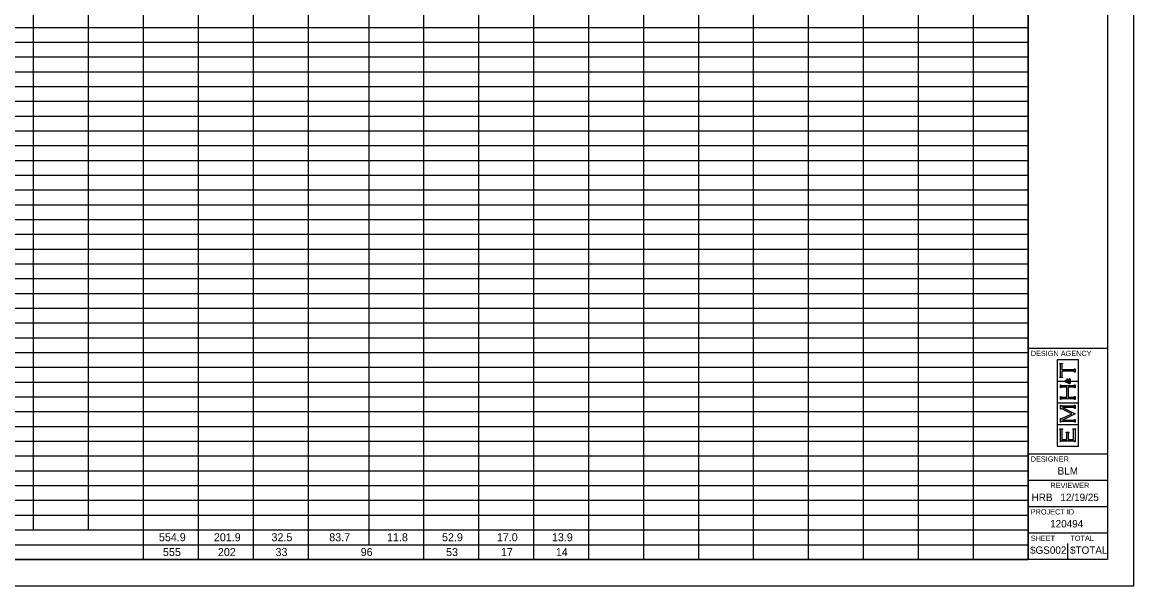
# Model space of a CAD drawing. Extents: x 0 to 34, y 0 to 22.
# Drawn here: x 12.96 to 34, y 0 to 10.67 of the extents above; entities that cross this region are included whole.
import ezdxf

# ---------------------------------------------------------------- set-up
doc = ezdxf.new("R2010")
doc.units = 0
for name, color, linetype in [('SH_Border', 7, 'Continuous'), ('SH_Cut_Line', 7, 'Continuous'), ('SH_Data', 7, 'Continuous'), ('SH_Text', 7, 'Continuous')]:
    doc.layers.add(name, color=color, linetype=linetype)

msp = doc.modelspace()

# ---------------------------------------------------------------- linework, layer by layer
at = {"layer": 'SH_Border'}
for p, q in [((32, 0.5), (32, 21.5)), ((32, 4.5), (33.5, 4.5)), ((32, 2.5), (33.5, 2.5)), ((32, 2), (33.5, 2)), ((32, 1.5), (33.5, 1.5)), ((32, 1), (33.5, 1))]:
    msp.add_line(p, q, dxfattribs=at)
msp.add_lwpolyline([(1.5, 21.5), (33.5, 21.5), (33.5, 0.5), (1.5, 0.5)], close=True, dxfattribs=at)
at = {"layer": 'SH_Cut_Line'}
msp.add_lwpolyline([(0, 0), (34, 0), (34, 22), (0, 22)], close=True, dxfattribs=at)
at = {"layer": 'SH_Data'}
for p, q in [((32.952, 4.279), (32.547, 4.279)), ((32.547, 4.279), (32.547, 3.875)), ((32.598, 4.204), (32.598, 4.211)), ((32.598, 4.211), (32.65, 4.211)), ((32.65, 4.211), (32.65, 4.204)), ((32.952, 3.875), (32.952, 4.279)), ((32.603, 4.203), (32.598, 4.204)), ((32.606, 4.201), (32.603, 4.203)), ((32.608, 4.199), (32.606, 4.201)), ((32.61, 4.196), (32.608, 4.199)), ((32.611, 4.192), (32.61, 4.196)), ((32.611, 4.187), (32.611, 4.192)), ((32.611, 3.968), (32.611, 4.187)), ((32.638, 4.196), (32.637, 4.192)), ((32.637, 4.192), (32.637, 4.187)), ((32.637, 4.187), (32.637, 4.093)), ((32.637, 4.093), (32.864, 4.093)), ((32.864, 4.061), (32.637, 4.061)), ((32.637, 4.061), (32.637, 3.968)), ((32.64, 4.199), (32.638, 4.196)), ((32.642, 4.201), (32.64, 4.199)), ((32.645, 4.203), (32.642, 4.201)), ((32.65, 4.204), (32.645, 4.203)), ((32.864, 4.093), (32.869, 4.093)), ((32.87, 4.061), (32.864, 4.061)), ((32.869, 4.093), (32.873, 4.094)), ((32.874, 4.06), (32.87, 4.061)), ((32.873, 4.094), (32.876, 4.096)), ((32.876, 4.059), (32.874, 4.06)), ((32.876, 4.096), (32.878, 4.097)), ((32.878, 4.057), (32.876, 4.059)), ((32.878, 4.097), (32.88, 4.101)), ((32.88, 4.053), (32.878, 4.057)), ((32.88, 4.101), (32.881, 4.106)), ((32.881, 4.048), (32.88, 4.053)), ((32.881, 4.106), (32.888, 4.106)), ((32.888, 4.048), (32.881, 4.048)), ((32.888, 4.106), (32.888, 4.048)), ((32.547, 3.875), (32.696, 3.875)), ((32.696, 3.869), (32.547, 3.869)), ((32.547, 3.869), (32.547, 3.465)), ((32.598, 3.95), (32.603, 3.951)), ((32.598, 3.944), (32.598, 3.95)), ((32.65, 3.944), (32.598, 3.944)), ((32.603, 3.951), (32.606, 3.953)), ((32.606, 3.953), (32.608, 3.955)), ((32.608, 3.955), (32.61, 3.958)), ((32.61, 3.958), (32.611, 3.962)), ((32.611, 3.962), (32.611, 3.968)), ((32.611, 3.749), (32.611, 3.807)), ((32.611, 3.807), (32.617, 3.807)), ((32.617, 3.807), (32.619, 3.802)), ((32.619, 3.802), (32.62, 3.798)), ((32.62, 3.798), (32.623, 3.797)), ((32.623, 3.797), (32.625, 3.795)), ((32.625, 3.795), (32.629, 3.794)), ((32.629, 3.794), (32.635, 3.794)), ((32.635, 3.794), (32.864, 3.794)), ((32.637, 3.968), (32.637, 3.962)), ((32.637, 3.962), (32.638, 3.958)), ((32.638, 3.958), (32.64, 3.955)), ((32.64, 3.955), (32.642, 3.953)), ((32.642, 3.953), (32.645, 3.951)), ((32.645, 3.951), (32.65, 3.95)), ((32.65, 3.95), (32.65, 3.944)), ((32.696, 3.875), (32.696, 3.869)), ((32.703, 3.879), (32.705, 3.883)), ((32.703, 3.873), (32.703, 3.879)), ((32.703, 3.868), (32.703, 3.873)), ((32.705, 3.863), (32.703, 3.868)), ((32.705, 3.883), (32.708, 3.887)), ((32.708, 3.858), (32.705, 3.863)), ((32.708, 3.887), (32.711, 3.89)), ((32.709, 3.879), (32.708, 3.876)), ((32.708, 3.876), (32.708, 3.873)), ((32.708, 3.873), (32.708, 3.869)), ((32.708, 3.869), (32.71, 3.866)), ((32.712, 3.853), (32.708, 3.858)), ((32.712, 3.881), (32.709, 3.879)), ((32.71, 3.866), (32.712, 3.864)), ((32.711, 3.89), (32.715, 3.892)), ((32.714, 3.883), (32.712, 3.881)), ((32.712, 3.864), (32.715, 3.862)), ((32.718, 3.85), (32.712, 3.853)), ((32.716, 3.884), (32.714, 3.883)), ((32.715, 3.892), (32.72, 3.892)), ((32.715, 3.862), (32.718, 3.861)), ((32.72, 3.884), (32.716, 3.884)), ((32.718, 3.861), (32.721, 3.861)), ((32.726, 3.85), (32.718, 3.85)), ((32.72, 3.892), (32.725, 3.892)), ((32.724, 3.884), (32.72, 3.884)), ((32.721, 3.861), (32.723, 3.861)), ((32.723, 3.861), (32.725, 3.862)), ((32.728, 3.882), (32.724, 3.884)), ((32.725, 3.892), (32.729, 3.89)), ((32.725, 3.862), (32.728, 3.862)), ((32.729, 3.85), (32.726, 3.85)), ((32.731, 3.88), (32.728, 3.882)), ((32.728, 3.862), (32.731, 3.863)), ((32.729, 3.89), (32.732, 3.887)), ((32.731, 3.85), (32.729, 3.85)), ((32.734, 3.877), (32.731, 3.88)), ((32.731, 3.863), (32.735, 3.865)), ((32.734, 3.851), (32.731, 3.85)), ((32.732, 3.887), (32.736, 3.883)), ((32.737, 3.872), (32.734, 3.877)), ((32.737, 3.852), (32.734, 3.851)), ((32.735, 3.865), (32.74, 3.867)), ((32.736, 3.883), (32.74, 3.878)), ((32.74, 3.867), (32.737, 3.872)), ((32.741, 3.853), (32.737, 3.852)), ((32.738, 3.893), (32.738, 3.922)), ((32.738, 3.922), (32.741, 3.922)), ((32.741, 3.893), (32.738, 3.893)), ((32.74, 3.878), (32.744, 3.869)), ((32.741, 3.922), (32.741, 3.918)), ((32.741, 3.918), (32.742, 3.915)), ((32.742, 3.896), (32.741, 3.895)), ((32.741, 3.895), (32.741, 3.893)), ((32.746, 3.855), (32.741, 3.853)), ((32.742, 3.915), (32.743, 3.913)), ((32.743, 3.897), (32.742, 3.896)), ((32.743, 3.913), (32.745, 3.911)), ((32.745, 3.899), (32.743, 3.897)), ((32.744, 3.869), (32.754, 3.875)), ((32.745, 3.911), (32.749, 3.908)), ((32.746, 3.899), (32.745, 3.899)), ((32.748, 3.899), (32.746, 3.899)), ((32.752, 3.844), (32.746, 3.855)), ((32.755, 3.899), (32.748, 3.899)), ((32.749, 3.908), (32.756, 3.904)), ((32.756, 3.86), (32.751, 3.857)), ((32.751, 3.857), (32.754, 3.852)), ((32.757, 3.837), (32.752, 3.844)), ((32.754, 3.875), (32.764, 3.881)), ((32.754, 3.852), (32.757, 3.848)), ((32.763, 3.895), (32.755, 3.899)), ((32.756, 3.904), (32.763, 3.9)), ((32.761, 3.863), (32.756, 3.86)), ((32.757, 3.848), (32.761, 3.845)), ((32.763, 3.833), (32.757, 3.837)), ((32.764, 3.865), (32.761, 3.863)), ((32.761, 3.845), (32.765, 3.843)), ((32.763, 3.9), (32.77, 3.896)), ((32.772, 3.887), (32.763, 3.895)), ((32.768, 3.829), (32.763, 3.833)), ((32.764, 3.881), (32.772, 3.887)), ((32.768, 3.867), (32.764, 3.865)), ((32.765, 3.843), (32.769, 3.841)), ((32.774, 3.872), (32.768, 3.867)), ((32.774, 3.827), (32.768, 3.829)), ((32.769, 3.841), (32.773, 3.841)), ((32.77, 3.896), (32.776, 3.891)), ((32.773, 3.841), (32.778, 3.841)), ((32.782, 3.878), (32.774, 3.872)), ((32.779, 3.827), (32.774, 3.827)), ((32.776, 3.891), (32.781, 3.895)), ((32.778, 3.841), (32.782, 3.843)), ((32.779, 3.923), (32.781, 3.926)), ((32.782, 3.922), (32.779, 3.923)), ((32.785, 3.827), (32.779, 3.827)), ((32.781, 3.926), (32.787, 3.924)), ((32.781, 3.895), (32.784, 3.898)), ((32.785, 3.921), (32.782, 3.922)), ((32.786, 3.873), (32.782, 3.878)), ((32.782, 3.843), (32.786, 3.846)), ((32.784, 3.898), (32.786, 3.901)), ((32.786, 3.919), (32.785, 3.921)), ((32.79, 3.829), (32.785, 3.827)), ((32.788, 3.917), (32.786, 3.919)), ((32.786, 3.901), (32.788, 3.904)), ((32.791, 3.886), (32.786, 3.881)), ((32.786, 3.881), (32.791, 3.876)), ((32.788, 3.869), (32.786, 3.873)), ((32.786, 3.846), (32.789, 3.849)), ((32.787, 3.924), (32.792, 3.921)), ((32.789, 3.914), (32.788, 3.917)), ((32.788, 3.904), (32.789, 3.908)), ((32.79, 3.867), (32.788, 3.869)), ((32.789, 3.911), (32.789, 3.914)), ((32.789, 3.908), (32.789, 3.911)), ((32.789, 3.849), (32.791, 3.853)), ((32.791, 3.864), (32.79, 3.867)), ((32.793, 3.834), (32.79, 3.829)), ((32.794, 3.89), (32.791, 3.886)), ((32.791, 3.876), (32.795, 3.87)), ((32.791, 3.861), (32.791, 3.864)), ((32.791, 3.859), (32.791, 3.861)), ((32.791, 3.853), (32.791, 3.859)), ((32.792, 3.921), (32.795, 3.918)), ((32.797, 3.838), (32.793, 3.834)), ((32.796, 3.894), (32.794, 3.89)), ((32.795, 3.918), (32.798, 3.914)), ((32.795, 3.87), (32.797, 3.866)), ((32.798, 3.897), (32.796, 3.894)), ((32.797, 3.866), (32.798, 3.861)), ((32.799, 3.844), (32.797, 3.838)), ((32.798, 3.914), (32.799, 3.91)), ((32.799, 3.901), (32.798, 3.897)), ((32.798, 3.861), (32.799, 3.857)), ((32.799, 3.91), (32.799, 3.905)), ((32.799, 3.905), (32.799, 3.901)), ((32.803, 3.869), (32.799, 3.875)), ((32.799, 3.875), (32.952, 3.875)), ((32.799, 3.857), (32.799, 3.852)), ((32.799, 3.852), (32.799, 3.844)), ((32.952, 3.869), (32.803, 3.869)), ((32.864, 3.794), (32.869, 3.794)), ((32.869, 3.794), (32.873, 3.795)), ((32.873, 3.795), (32.876, 3.797)), ((32.876, 3.797), (32.878, 3.798)), ((32.878, 3.798), (32.88, 3.802)), ((32.88, 3.802), (32.881, 3.807)), ((32.881, 3.807), (32.888, 3.807)), ((32.888, 3.807), (32.888, 3.749)), ((32.952, 3.465), (32.952, 3.869)), ((32.617, 3.749), (32.611, 3.749)), ((32.611, 3.527), (32.611, 3.585)), ((32.611, 3.585), (32.617, 3.585)), ((32.618, 3.754), (32.617, 3.749)), ((32.617, 3.585), (32.619, 3.58)), ((32.62, 3.758), (32.618, 3.754)), ((32.619, 3.58), (32.62, 3.576)), ((32.623, 3.76), (32.62, 3.758)), ((32.625, 3.761), (32.623, 3.76)), ((32.629, 3.762), (32.625, 3.761)), ((32.635, 3.762), (32.629, 3.762)), ((32.732, 3.762), (32.635, 3.762)), ((32.732, 3.572), (32.732, 3.762)), ((32.864, 3.762), (32.759, 3.762)), ((32.759, 3.762), (32.759, 3.572)), ((32.87, 3.762), (32.864, 3.762)), ((32.874, 3.761), (32.87, 3.762)), ((32.876, 3.76), (32.874, 3.761)), ((32.878, 3.758), (32.876, 3.76)), ((32.88, 3.754), (32.878, 3.758)), ((32.878, 3.576), (32.88, 3.58)), ((32.881, 3.749), (32.88, 3.754)), ((32.88, 3.58), (32.881, 3.585)), ((32.888, 3.749), (32.881, 3.749)), ((32.881, 3.585), (32.888, 3.585)), ((32.888, 3.585), (32.888, 3.527)), ((32.547, 3.465), (32.952, 3.465)), ((32.952, 3.459), (32.547, 3.459)), ((32.547, 3.459), (32.547, 3.055)), ((32.617, 3.527), (32.611, 3.527)), ((32.611, 3.345), (32.611, 3.418)), ((32.611, 3.418), (32.617, 3.418)), ((32.618, 3.532), (32.617, 3.527)), ((32.617, 3.418), (32.619, 3.412)), ((32.62, 3.536), (32.618, 3.532)), ((32.619, 3.412), (32.62, 3.409)), ((32.62, 3.576), (32.623, 3.574)), ((32.623, 3.537), (32.62, 3.536)), ((32.62, 3.409), (32.623, 3.407)), ((32.623, 3.574), (32.625, 3.573)), ((32.625, 3.539), (32.623, 3.537)), ((32.623, 3.407), (32.625, 3.405)), ((32.625, 3.573), (32.629, 3.572)), ((32.629, 3.54), (32.625, 3.539)), ((32.625, 3.405), (32.629, 3.405)), ((32.629, 3.572), (32.635, 3.572)), ((32.635, 3.54), (32.629, 3.54)), ((32.629, 3.405), (32.635, 3.405)), ((32.635, 3.572), (32.732, 3.572)), ((32.864, 3.54), (32.635, 3.54)), ((32.635, 3.405), (32.864, 3.405)), ((32.864, 3.373), (32.654, 3.373)), ((32.654, 3.373), (32.888, 3.255)), ((32.75, 3.5), (32.75, 3.5)), ((32.759, 3.572), (32.864, 3.572)), ((32.864, 3.572), (32.87, 3.572)), ((32.87, 3.54), (32.864, 3.54)), ((32.864, 3.405), (32.869, 3.405)), ((32.87, 3.373), (32.864, 3.373)), ((32.869, 3.405), (32.873, 3.405)), ((32.87, 3.572), (32.874, 3.573)), ((32.874, 3.539), (32.87, 3.54)), ((32.874, 3.372), (32.87, 3.373)), ((32.873, 3.405), (32.876, 3.407)), ((32.874, 3.573), (32.876, 3.574)), ((32.876, 3.538), (32.874, 3.539)), ((32.876, 3.37), (32.874, 3.372)), ((32.876, 3.574), (32.878, 3.576)), ((32.878, 3.536), (32.876, 3.538)), ((32.876, 3.407), (32.878, 3.409)), ((32.878, 3.369), (32.876, 3.37)), ((32.88, 3.532), (32.878, 3.536)), ((32.878, 3.409), (32.88, 3.412)), ((32.88, 3.365), (32.878, 3.369)), ((32.881, 3.527), (32.88, 3.532)), ((32.88, 3.412), (32.881, 3.418)), ((32.888, 3.527), (32.881, 3.527)), ((32.881, 3.418), (32.888, 3.418)), ((32.888, 3.418), (32.888, 3.36)), ((32.952, 3.055), (32.952, 3.459)), ((32.617, 3.345), (32.611, 3.345)), ((32.611, 3.096), (32.611, 3.168)), ((32.611, 3.168), (32.617, 3.168)), ((32.62, 3.352), (32.617, 3.345)), ((32.617, 3.168), (32.62, 3.162)), ((32.622, 3.355), (32.62, 3.352)), ((32.62, 3.162), (32.622, 3.158)), ((32.626, 3.355), (32.622, 3.355)), ((32.622, 3.158), (32.626, 3.158)), ((32.629, 3.355), (32.626, 3.355)), ((32.626, 3.158), (32.627, 3.158)), ((32.627, 3.158), (32.633, 3.161)), ((32.633, 3.353), (32.629, 3.355)), ((32.64, 3.35), (32.633, 3.353)), ((32.633, 3.161), (32.641, 3.165)), ((32.825, 3.257), (32.64, 3.35)), ((32.641, 3.165), (32.825, 3.257)), ((32.888, 3.255), (32.654, 3.138)), ((32.881, 3.36), (32.88, 3.365)), ((32.888, 3.36), (32.881, 3.36)), ((32.547, 3.055), (32.952, 3.055)), ((32.952, 3.049), (32.547, 3.049)), ((32.547, 3.049), (32.547, 2.645)), ((32.598, 2.962), (32.598, 2.969)), ((32.598, 2.969), (32.65, 2.969)), ((32.603, 2.961), (32.598, 2.962)), ((32.606, 2.959), (32.603, 2.961)), ((32.608, 2.957), (32.606, 2.959)), ((32.61, 2.955), (32.608, 2.957)), ((32.611, 2.951), (32.61, 2.955)), ((32.617, 3.096), (32.611, 3.096)), ((32.611, 2.945), (32.611, 2.951)), ((32.618, 3.102), (32.617, 3.096)), ((32.62, 3.105), (32.618, 3.102)), ((32.623, 3.107), (32.62, 3.105)), ((32.625, 3.109), (32.623, 3.107)), ((32.629, 3.109), (32.625, 3.109)), ((32.635, 3.109), (32.629, 3.109)), ((32.864, 3.109), (32.635, 3.109)), ((32.64, 2.957), (32.638, 2.955)), ((32.638, 2.955), (32.638, 2.951)), ((32.638, 2.951), (32.638, 2.945)), ((32.642, 2.959), (32.64, 2.957)), ((32.645, 2.961), (32.642, 2.959)), ((32.65, 2.962), (32.645, 2.961)), ((32.65, 2.969), (32.65, 2.962)), ((32.654, 3.138), (32.864, 3.138)), ((32.848, 2.965), (32.848, 2.972)), ((32.848, 2.972), (32.901, 2.972)), ((32.853, 2.964), (32.848, 2.965)), ((32.857, 2.962), (32.853, 2.964)), ((32.859, 2.96), (32.857, 2.962)), ((32.86, 2.958), (32.859, 2.96)), ((32.861, 2.953), (32.86, 2.958)), ((32.861, 2.948), (32.861, 2.953)), ((32.861, 2.77), (32.861, 2.948)), ((32.864, 3.138), (32.869, 3.138)), ((32.87, 3.109), (32.864, 3.109)), ((32.869, 3.138), (32.873, 3.139)), ((32.874, 3.109), (32.87, 3.109)), ((32.873, 3.139), (32.876, 3.141)), ((32.876, 3.107), (32.874, 3.109)), ((32.876, 3.141), (32.878, 3.143)), ((32.878, 3.105), (32.876, 3.107)), ((32.878, 3.143), (32.88, 3.146)), ((32.88, 3.102), (32.878, 3.105)), ((32.88, 3.146), (32.881, 3.151)), ((32.881, 3.096), (32.88, 3.102)), ((32.881, 3.151), (32.888, 3.151)), ((32.888, 3.096), (32.881, 3.096)), ((32.888, 3.151), (32.888, 3.096)), ((32.889, 2.957), (32.888, 2.953)), ((32.888, 2.953), (32.888, 2.948)), ((32.888, 2.948), (32.888, 2.725)), ((32.891, 2.96), (32.889, 2.957)), ((32.892, 2.962), (32.891, 2.96)), ((32.896, 2.964), (32.892, 2.962)), ((32.901, 2.965), (32.896, 2.964)), ((32.901, 2.972), (32.901, 2.965)), ((32.952, 2.645), (32.952, 3.049)), ((32.611, 2.725), (32.611, 2.945)), ((32.623, 2.735), (32.62, 2.734)), ((32.625, 2.737), (32.623, 2.735)), ((32.629, 2.738), (32.625, 2.737)), ((32.635, 2.738), (32.629, 2.738)), ((32.864, 2.738), (32.635, 2.738)), ((32.638, 2.945), (32.638, 2.77)), ((32.638, 2.77), (32.732, 2.77)), ((32.719, 2.902), (32.719, 2.908)), ((32.719, 2.908), (32.772, 2.908)), ((32.724, 2.901), (32.719, 2.902)), ((32.728, 2.899), (32.724, 2.901)), ((32.729, 2.896), (32.728, 2.899)), ((32.731, 2.894), (32.729, 2.896)), ((32.732, 2.89), (32.731, 2.894)), ((32.732, 2.884), (32.732, 2.89)), ((32.732, 2.77), (32.732, 2.884)), ((32.76, 2.894), (32.759, 2.89)), ((32.759, 2.89), (32.759, 2.884)), ((32.759, 2.884), (32.759, 2.77)), ((32.759, 2.77), (32.861, 2.77)), ((32.761, 2.896), (32.76, 2.894)), ((32.763, 2.899), (32.761, 2.896)), ((32.767, 2.901), (32.763, 2.899)), ((32.772, 2.902), (32.767, 2.901)), ((32.772, 2.908), (32.772, 2.902)), ((32.87, 2.738), (32.864, 2.738)), ((32.874, 2.737), (32.87, 2.738)), ((32.876, 2.735), (32.874, 2.737)), ((32.878, 2.734), (32.876, 2.735)), ((32.547, 2.645), (32.952, 2.645)), ((32.617, 2.725), (32.611, 2.725)), ((32.619, 2.73), (32.617, 2.725)), ((32.62, 2.734), (32.619, 2.73)), ((32.88, 2.73), (32.878, 2.734)), ((32.881, 2.725), (32.88, 2.73)), ((32.888, 2.725), (32.881, 2.725)), ((32.375, 0.675), (32.375, 0.675)), ((32.75, 0.5), (32.75, 0.8))]:
    msp.add_line(p, q, dxfattribs=at)
at = {"layer": 'SH_Text'}
for p, q in [((13.171, 21.488), (13.171, 1.058)), ((14.211, 21.488), (14.211, 1.058)), ((15.251, 21.488), (15.251, 0.499)), ((16.291, 21.488), (16.291, 0.499)), ((17.331, 21.488), (17.331, 0.499)), ((18.371, 21.488), (18.371, 0.499)), ((19.519, 21.488), (19.519, 0.778)), ((20.559, 21.488), (20.559, 0.499)), ((21.599, 21.488), (21.599, 0.499)), ((22.639, 21.488), (22.639, 0.499)), ((23.679, 21.488), (23.679, 0.499)), ((24.719, 21.488), (24.719, 0.499)), ((25.759, 21.488), (25.759, 0.499)), ((26.799, 21.488), (26.799, 0.499)), ((27.84, 21.488), (27.84, 0.499)), ((28.88, 21.488), (28.88, 0.499)), ((29.92, 21.488), (29.92, 0.499)), ((30.96, 21.488), (30.96, 0.499)), ((32, 21.488), (32, 0.499)), ((1.5, 10.574), (32, 10.574)), ((1.5, 10.294), (32, 10.294)), ((1.5, 10.014), (32, 10.014)), ((1.5, 9.734), (32, 9.734)), ((1.5, 9.454), (32, 9.454)), ((1.5, 9.174), (32, 9.174)), ((1.5, 8.895), (32, 8.895)), ((1.5, 8.615), (32, 8.615)), ((1.5, 8.335), (32, 8.335)), ((1.5, 8.055), (32, 8.055)), ((1.5, 7.775), (32, 7.775)), ((1.5, 7.495), (32, 7.495)), ((1.5, 7.215), (32, 7.215)), ((1.5, 6.935), (32, 6.935)), ((1.5, 6.656), (32, 6.656)), ((1.5, 6.376), (32, 6.376)), ((1.5, 6.096), (32, 6.096)), ((1.5, 5.816), (32, 5.816)), ((1.5, 5.536), (32, 5.536)), ((1.5, 5.256), (32, 5.256)), ((1.5, 4.976), (32, 4.976)), ((1.5, 4.697), (32, 4.697)), ((1.5, 4.417), (32, 4.417)), ((1.5, 4.137), (32, 4.137)), ((1.5, 3.857), (32, 3.857)), ((1.5, 3.577), (32, 3.577)), ((1.5, 3.297), (32, 3.297)), ((1.5, 3.017), (32, 3.017)), ((1.5, 2.738), (32, 2.738)), ((1.5, 2.458), (32, 2.458)), ((1.5, 2.178), (32, 2.178)), ((1.5, 1.898), (32, 1.898)), ((1.5, 1.618), (32, 1.618)), ((1.5, 1.338), (32, 1.338)), ((1.5, 1.058), (32, 1.058)), ((1.5, 0.778), (32, 0.778)), ((1.5, 0.499), (32, 0.499))]:
    msp.add_line(p, q, dxfattribs=at)

# ---------------------------------------------------------------- texts
at = {"layer": 'SH_Data'}
for s, height, p in [('DESIGN AGENCY', 0.1, (32.05, 4.35)), ('DESIGNER', 0.1, (32.05, 2.35)), ('BLM', 0.14, (32.559, 2.105)), ('REVIEWER', 0.1, (32.422, 1.85)), ('HRB', 0.14, (32.066, 1.605)), ('12/19/25', 0.14, (32.611, 1.605)), ('PROJECT ID', 0.1, (32.05, 1.35)), ('120494', 0.14, (32.418, 1.105)), ('SHEET', 0.1, (32.05, 0.85)), ('TOTAL', 0.1, (32.8, 0.85)), ('$GS002', 0.14, (32.037, 0.605)), ('$TOTAL', 0.14, (32.794, 0.605))]:
    msp.add_text(s, height=height, dxfattribs=at).set_placement(p)
at = {"layer": 'SH_Text'}
for s, p in [('554.9', (15.549, 0.843)), ('201.9', (16.589, 0.843)), ('32.5', (17.68, 0.843)), ('83.7', (18.773, 0.843)), ('11.8', (19.866, 0.843)), ('52.9', (20.907, 0.843)), ('17.0', (21.945, 0.843)), ('13.9', (22.987, 0.843)), ('555', (15.625, 0.563)), ('202', (16.665, 0.563)), ('33', (17.756, 0.563)), ('96', (19.368, 0.563)), ('53', (20.984, 0.563)), ('17', (22.022, 0.563)), ('14', (23.061, 0.563))]:
    msp.add_text(s, height=0.1515, dxfattribs=at).set_placement(p)

doc.saveas('drawing.dxf')
